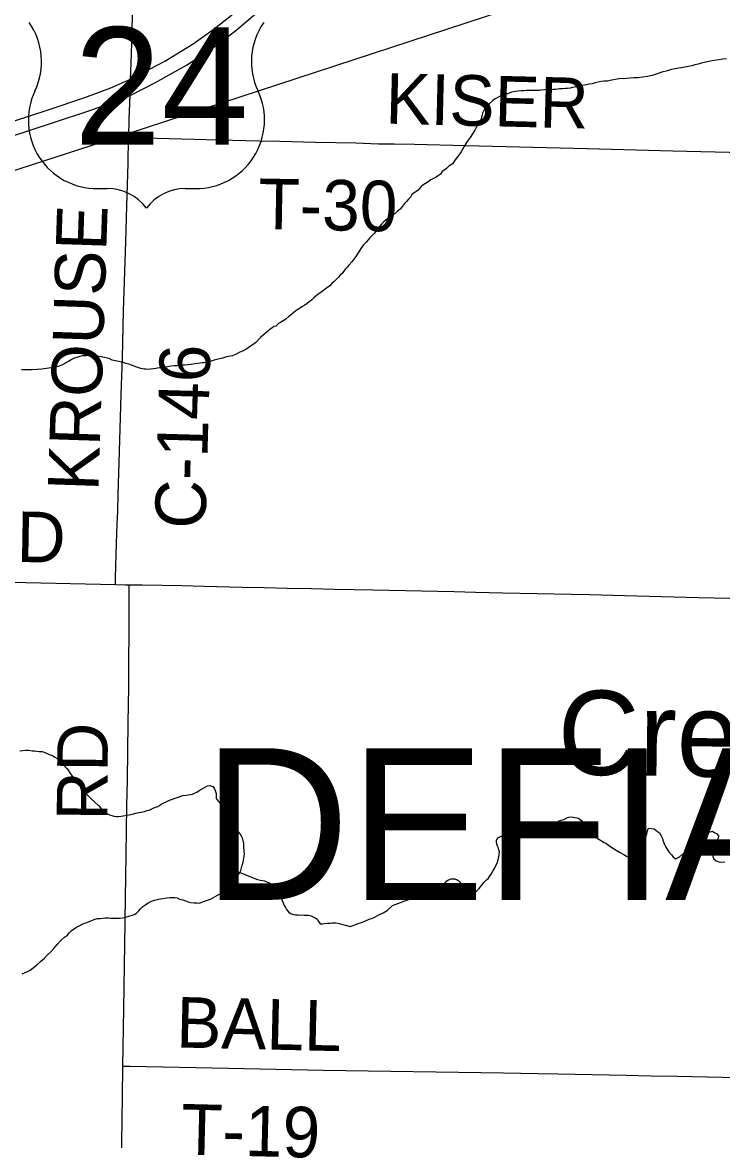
# Model space of a CAD drawing. Extents: x -483 to 680, y 0 to 440.
# Drawn here: x 121.3 to 160.7, y 248.8 to 311.6 of the extents above; entities that cross this region are included whole.
import ezdxf

# ---------------------------------------------------------------- set-up
doc = ezdxf.new("R2010")
doc.units = 0
for name, color, linetype in [('GM_X_County_Road', 7, 'Continuous'), ('GM_X_County_Road_Text', 7, 'Continuous'), ('GM_X_Minor_River', 7, 'Continuous'), ('GM_X_Minor_River_Text', 7, 'Continuous'), ('GM_X_Rail_Line', 7, 'Continuous'), ('GM_X_Township_Road', 7, 'Continuous'), ('GM_X_Township_Road_Text', 7, 'Continuous'), ('GM_X_Township_Text', 7, 'Continuous'), ('GM_X_US_Location', 7, 'Continuous'), ('GM_X_US_Route', 7, 'Continuous'), ('GM_X_US_Shield', 7, 'Continuous')]:
    doc.layers.add(name, color=color, linetype=linetype)

msp = doc.modelspace()

# ---------------------------------------------------------------- linework, layer by layer
at = {"layer": 'GM_X_County_Road'}
msp.add_line((127.32, 305.184), (127.345, 306.207), dxfattribs=at)
for points in [[(127.345, 306.207), (127.389, 307.543), (127.421, 308.449), (127.455, 309.354), (127.488, 310.473), (127.534, 312.026), (127.602, 314.637), (127.71, 318.272), (127.783, 320.572), (127.837, 322.374), (127.915, 324.829), (127.974, 326.631), (128.012, 327.812), (128.049, 329.241), (128.125, 331.945), (128.218, 335.032), (128.223, 336.234), (128.255, 337.539), (128.291, 339.124), (128.329, 340.865), (128.373, 342.512), (128.399, 343.693), (128.417, 344.657), (128.523, 349.753)], [(126.566, 280.056), (126.576, 280.424), (126.629, 282.382), (126.671, 283.468), (126.692, 284.183), (126.718, 285.115), (126.791, 287.537), (126.89, 290.737), (126.958, 292.787), (127.024, 295.427), (127.154, 299.309), (127.206, 301.329), (127.276, 303.72), (127.289, 304.124), (127.308, 304.745), (127.32, 305.184)], [(77.163, 281.006), (79.053, 280.972), (84.585, 280.875), (89.278, 280.783), (90.894, 280.761), (92.697, 280.726), (94.033, 280.704), (94.748, 280.692), (95.649, 280.674), (99.658, 280.588), (101.585, 280.553), (106.278, 280.468), (107.954, 280.425), (111.436, 280.37), (117.186, 280.256), (121.537, 280.166), (124.893, 280.092), (126.566, 280.056)], [(126.566, 280.056), (127.131, 280.044), (127.339, 280.04)], [(126.984, 252.996), (127.036, 256.212), (127.094, 259.847), (127.129, 262.427), (127.164, 264.85), (127.21, 267.615), (127.24, 269.076), (127.283, 272.276), (127.311, 274.295), (127.34, 278.798), (127.339, 280.04)], [(127.339, 280.04), (128.063, 280.038), (130.301, 279.993), (131.543, 279.96), (133.688, 279.907), (134.931, 279.884), (136.205, 279.855), (137.573, 279.829), (138.878, 279.8), (141.022, 279.752), (145.591, 279.656), (146.802, 279.622), (148.326, 279.586), (152.179, 279.515), (153.235, 279.487), (155.162, 279.431), (159.327, 279.332), (161.968, 279.265)], [(126.559, 227.882), (126.563, 228.311), (126.663, 233.22), (126.683, 234.619), (126.701, 235.985), (126.731, 237.85), (126.777, 240.833), (126.836, 243.317), (126.864, 244.529), (126.889, 246.518), (126.941, 249.874), (126.983, 252.888), (126.984, 252.996)]]:
    msp.add_lwpolyline(points, dxfattribs=at)
at = {"layer": 'GM_X_Minor_River'}
for points in [[(159.476, 309.352), (159.304, 309.3), (159.113, 309.248), (158.941, 309.195), (158.75, 309.162), (158.559, 309.129), (158.368, 309.096), (158.197, 309.062), (158.006, 309.029), (157.815, 308.996), (157.585, 308.926), (157.26, 308.839), (156.992, 308.751), (156.724, 308.663), (156.456, 308.594), (156.171, 308.563), (155.942, 308.531), (155.695, 308.518), (155.486, 308.505), (155.276, 308.491), (155.105, 308.476), (154.934, 308.481), (154.762, 308.447), (154.553, 308.414), (154.362, 308.381), (154.209, 308.347), (154.019, 308.333), (153.847, 308.319), (153.695, 308.285), (153.523, 308.251), (153.351, 308.198), (153.179, 308.165), (153.007, 308.131), (152.912, 308.115), (152.721, 308.081), (152.549, 308.048), (152.453, 308.012), (152.358, 307.996), (152.244, 307.98), (152.11, 307.945), (151.958, 307.93), (151.825, 307.933), (151.691, 307.918), (151.52, 307.903), (151.425, 307.887), (151.291, 307.871), (151.158, 307.875), (151.006, 307.859), (150.873, 307.863), (150.759, 307.866), (150.664, 307.849), (150.493, 307.835), (150.397, 307.818), (150.245, 307.822), (150.151, 307.824), (150.036, 307.808), (149.865, 307.813), (149.751, 307.815), (149.638, 307.819), (149.504, 307.803), (149.352, 307.788), (149.2, 307.773), (149.047, 307.758), (148.933, 307.742), (148.818, 307.725), (148.684, 307.672), (148.588, 307.636), (148.493, 307.62), (148.378, 307.585), (148.282, 307.53), (148.148, 307.477), (148.013, 307.404), (147.859, 307.332), (147.743, 307.24), (147.587, 307.092), (147.489, 306.981), (147.392, 306.888), (147.294, 306.758), (147.193, 306.533), (147.172, 306.438), (147.132, 306.344), (147.109, 306.212), (147.05, 306.119), (146.97, 305.969), (146.911, 305.875), (146.832, 305.744), (146.752, 305.594), (146.633, 305.388), (146.495, 305.183), (146.377, 305.015), (146.297, 304.884), (146.159, 304.66), (146.08, 304.529), (146, 304.398), (145.921, 304.248), (145.783, 304.081), (145.646, 303.913), (145.508, 303.689), (145.296, 303.562), (145.159, 303.432), (145.024, 303.322)], [(160.888, 309.601), (160.678, 309.569), (160.468, 309.536), (160.221, 309.504), (159.973, 309.454), (159.743, 309.403), (159.476, 309.352)], [(145.024, 303.322), (144.927, 303.267), (144.829, 303.118), (144.713, 303.045), (144.578, 302.953), (144.404, 302.844), (144.289, 302.79), (144.134, 302.68), (143.845, 302.497), (143.748, 302.424), (143.67, 302.331), (143.572, 302.219), (143.224, 301.962), (143.163, 301.831), (143.027, 301.702), (142.91, 301.572), (142.812, 301.46), (142.694, 301.311), (142.557, 301.144), (142.402, 301.015), (142.266, 300.886), (142.131, 300.813), (141.938, 300.685), (141.783, 300.556), (141.627, 300.408), (141.53, 300.316), (141.413, 300.186), (141.295, 300.037), (141.216, 299.925), (141.118, 299.794), (140.982, 299.665), (140.865, 299.535), (140.767, 299.424), (140.65, 299.294), (140.513, 299.164), (140.395, 298.996), (140.079, 298.492), (139.961, 298.343), (139.843, 298.194), (139.687, 298.008), (139.589, 297.897), (139.511, 297.804), (139.374, 297.636), (139.295, 297.524), (139.198, 297.432), (139.1, 297.32), (138.964, 297.191), (138.847, 297.08), (138.73, 296.969), (138.613, 296.839), (138.42, 296.711), (138.265, 296.601), (138.11, 296.472), (137.955, 296.362), (137.82, 296.252), (137.703, 296.16), (137.586, 296.03), (137.451, 295.938), (137.335, 295.846), (137.199, 295.755), (137.084, 295.682), (136.929, 295.591), (136.814, 295.518), (136.697, 295.426), (136.601, 295.353), (136.484, 295.242), (136.31, 295.113), (136.135, 294.966), (135.981, 294.875), (135.846, 294.783), (135.73, 294.729), (135.575, 294.581), (135.479, 294.546), (135.363, 294.473), (135.247, 294.381), (135.111, 294.27), (134.956, 294.141), (134.859, 294.068), (134.723, 293.938), (134.45, 293.661), (134.295, 293.551), (134.16, 293.44), (134.005, 293.33), (133.851, 293.239), (133.697, 293.167), (133.563, 293.114), (133.39, 293.023), (133.139, 292.897), (132.815, 292.848), (132.586, 292.778), (132.338, 292.727), (132.108, 292.657), (131.897, 292.587), (131.706, 292.554), (131.554, 292.52), (131.439, 292.504), (131.325, 292.488), (131.192, 292.472), (131.02, 292.457), (130.829, 292.424), (130.639, 292.391)], [(130.639, 292.391), (130.449, 292.377), (130.278, 292.381), (130.144, 292.366), (130.011, 292.35), (129.859, 292.335), (129.687, 292.321), (129.516, 292.287), (129.344, 292.273), (129.21, 292.238), (129.115, 292.221), (129.02, 292.224), (128.925, 292.207), (128.829, 292.191), (128.696, 292.175), (128.544, 292.16), (128.429, 292.144), (128.277, 292.148), (128.183, 292.151), (128.088, 292.172), (127.994, 292.193), (127.881, 292.234), (127.768, 292.275), (127.617, 292.317), (127.467, 292.378), (127.316, 292.439), (127.146, 292.481), (126.995, 292.523), (126.561, 292.629), (126.391, 292.671), (126.222, 292.752), (125.958, 292.815), (125.769, 292.858), (125.561, 292.883), (125.409, 292.906), (125.277, 292.909), (125.182, 292.911), (125.087, 292.914), (124.992, 292.916), (124.897, 292.9), (124.802, 292.902), (124.707, 292.905), (124.573, 292.87), (124.458, 292.835), (124.324, 292.8), (124.209, 292.747), (124.074, 292.674), (123.92, 292.583), (123.785, 292.511), (123.67, 292.438), (123.554, 292.383), (123.343, 292.313), (123.171, 292.26), (122.943, 292.228), (122.695, 292.197), (122.428, 292.166), (122.161, 292.135), (121.895, 292.122), (121.61, 292.111), (121.439, 292.115), (121.287, 292.119)], [(121.189, 270.719), (121.361, 270.733), (121.532, 270.748), (121.703, 270.743), (121.892, 270.719), (122.025, 270.716), (122.138, 270.694), (122.29, 270.671), (122.442, 270.667), (122.649, 270.605), (122.836, 270.505), (123.025, 270.444), (123.156, 270.364), (123.287, 270.285), (123.399, 270.206), (123.547, 270.05), (123.658, 269.933), (123.75, 269.817), (123.842, 269.72), (123.916, 269.623), (124.007, 269.469), (124.136, 269.294), (124.246, 269.159), (124.338, 269.042), (124.43, 268.926), (124.504, 268.829), (124.577, 268.713), (124.725, 268.558), (124.78, 268.461), (124.909, 268.306), (125.184, 268.04)], [(129.609, 267.943), (130.357, 268.204), (130.547, 268.218), (130.643, 268.234), (130.757, 268.251), (130.891, 268.285), (131.006, 268.339), (131.14, 268.393), (131.276, 268.484), (131.43, 268.575), (131.603, 268.665), (131.738, 268.738), (131.871, 268.754), (132.041, 268.711), (132.115, 268.614), (132.168, 268.48), (132.221, 268.308), (132.233, 268.023), (132.341, 267.884)], [(125.184, 268.04), (125.632, 267.614), (125.724, 267.516), (125.872, 267.359), (126.02, 267.24), (126.113, 267.179), (126.226, 267.119), (126.358, 267.076), (126.47, 267.034), (126.604, 267.03), (126.718, 267.026), (126.89, 267.039), (127.119, 267.07), (127.33, 267.12), (127.579, 267.168), (127.79, 267.218), (128.02, 267.268), (128.193, 267.3), (128.328, 267.353), (128.462, 267.386), (128.578, 267.439), (128.694, 267.493), (128.81, 267.546), (128.906, 267.561), (129.041, 267.633), (129.139, 267.706), (129.607, 267.943)], [(132.347, 262.615), (132.482, 262.686), (132.579, 262.74), (132.659, 262.832), (132.758, 262.962), (132.897, 263.129), (133.054, 263.295), (133.212, 263.461), (133.369, 263.627), (133.488, 263.756), (133.549, 263.868), (133.609, 263.98), (133.652, 264.131), (133.695, 264.282), (133.738, 264.451), (133.81, 264.906), (133.797, 265.096), (133.786, 265.344), (133.772, 265.515), (133.739, 265.65), (133.706, 265.803), (133.652, 265.919), (133.58, 266.055), (133.47, 266.172), (133.379, 266.309), (133.232, 266.485), (133.104, 266.641), (132.994, 266.778), (132.921, 266.876), (132.867, 266.973), (132.813, 267.069), (132.778, 267.166), (132.724, 267.282), (132.671, 267.398), (132.618, 267.533), (132.564, 267.629), (132.454, 267.766), (132.341, 267.884)], [(147.675, 263.777), (147.776, 263.945), (147.857, 264.094), (147.918, 264.226), (147.998, 264.356), (148.039, 264.45), (148.063, 264.582), (148.106, 264.752), (148.134, 265.036), (148.1, 265.152), (148.084, 265.247), (148.031, 265.363), (147.995, 265.46), (147.981, 265.593), (147.984, 265.688), (148.045, 265.819), (148.238, 265.908), (148.352, 265.904), (148.561, 265.878), (148.656, 265.875), (148.751, 265.872), (148.904, 265.886), (149.018, 265.882), (149.171, 265.896), (149.323, 265.891), (149.514, 265.904), (149.744, 265.953), (149.897, 265.986), (150.032, 266.038), (150.226, 266.127), (150.457, 266.215), (150.689, 266.321), (150.882, 266.391), (151.017, 266.462), (151.115, 266.535), (151.288, 266.605), (151.484, 266.77), (151.753, 266.856), (151.928, 266.946), (152.043, 266.98), (152.196, 266.994), (152.291, 266.991), (152.574, 266.924), (152.779, 266.765), (152.872, 266.686), (152.964, 266.607), (153.056, 266.509), (153.202, 266.294), (153.311, 266.139), (153.421, 266.002), (153.513, 265.904), (153.624, 265.805), (153.811, 265.685), (153.923, 265.624), (154.016, 265.563), (154.11, 265.522), (154.259, 265.403), (154.389, 265.323), (154.539, 265.223), (154.707, 265.122), (154.894, 265.021), (155.137, 264.879), (155.287, 264.798), (155.4, 264.757), (155.513, 264.734), (155.609, 264.75), (155.802, 264.819), (155.978, 264.966), (156.076, 265.076), (156.136, 265.17), (156.179, 265.32), (156.222, 265.452), (156.263, 265.565), (156.306, 265.716), (156.348, 265.828), (156.39, 265.941), (156.412, 266.055), (156.435, 266.168), (156.477, 266.281), (156.518, 266.374), (156.84, 266.326), (157.026, 266.186), (157.138, 266.107), (157.227, 265.932), (157.298, 265.778), (157.314, 265.682), (157.367, 265.547), (157.421, 265.45), (157.475, 265.335), (157.529, 265.238), (157.583, 265.141), (157.656, 265.043), (157.803, 264.867), (157.894, 264.75), (158.024, 264.65), (158.14, 264.704), (158.256, 264.757), (158.432, 264.903), (158.567, 264.956), (158.724, 265.103), (158.804, 265.214)], [(158.804, 265.214), (158.884, 265.326), (158.964, 265.475), (159.044, 265.587), (159.182, 265.734), (159.281, 265.845), (159.418, 265.955), (159.534, 266.008), (159.726, 266.078), (159.919, 266.147), (160.111, 266.198), (160.241, 266.099), (160.335, 266.058), (160.446, 265.94), (160.422, 265.807), (160.381, 265.695), (160.339, 265.582), (160.298, 265.488), (160.256, 265.356), (160.232, 265.224), (160.191, 265.111), (160.148, 264.96), (160.123, 264.771), (160.194, 264.635), (160.325, 264.536), (160.475, 264.474), (160.627, 264.45), (160.799, 264.482)], [(133.549, 263.868), (134.545, 263.473), (134.716, 263.449), (134.848, 263.425), (134.943, 263.403), (135.055, 263.342), (135.225, 263.298), (135.393, 263.179), (135.504, 263.08), (135.558, 262.983), (135.631, 262.885), (135.741, 262.748), (135.832, 262.612), (135.885, 262.496), (135.936, 262.304), (135.989, 262.169), (136.041, 262.016), (136.113, 261.899), (136.168, 261.802), (136.296, 261.665), (136.408, 261.566), (136.577, 261.522), (136.691, 261.499), (136.824, 261.495), (136.957, 261.471), (137.052, 261.487), (137.167, 261.483), (137.281, 261.479), (137.414, 261.475), (137.565, 261.432), (137.678, 261.39), (137.79, 261.329), (137.902, 261.249), (137.974, 261.114), (138.065, 260.997), (138.198, 260.992), (138.313, 261.007), (138.466, 261.021), (138.638, 261.035), (138.733, 261.051), (138.828, 261.047), (138.943, 261.044), (139.056, 261.021), (139.208, 260.997), (139.34, 260.954), (139.472, 260.912), (139.566, 260.89), (139.755, 260.845), (139.928, 260.897), (140.14, 260.984), (140.391, 261.071), (140.622, 261.159), (140.815, 261.247), (141.008, 261.317), (141.201, 261.406), (141.395, 261.513), (141.607, 261.601), (141.84, 261.746), (142.135, 262.021), (142.579, 262.197), (142.829, 262.284), (143.002, 262.335), (143.137, 262.387), (143.291, 262.458), (143.447, 262.567), (143.661, 262.693), (143.835, 262.783), (143.99, 262.873), (144.106, 262.926), (144.279, 262.977), (144.393, 262.973), (144.546, 262.987), (144.68, 263.002), (144.776, 263.037), (144.893, 263.109), (145.089, 263.292), (145.188, 263.403), (145.285, 263.457), (145.42, 263.51), (145.534, 263.525), (145.629, 263.522), (145.761, 263.46), (145.91, 263.36), (145.999, 263.167), (145.993, 262.977), (145.95, 262.826), (145.965, 262.693), (146.058, 262.632), (146.153, 262.61), (146.266, 262.587), (146.381, 262.622), (146.535, 262.674), (146.67, 262.707), (146.826, 262.816), (147.002, 262.981), (147.141, 263.148), (147.261, 263.315), (147.418, 263.462), (147.516, 263.554), (147.576, 263.647), (147.675, 263.777)], [(121.332, 258.189), (121.583, 258.295), (121.776, 258.383), (121.952, 258.51), (122.148, 258.694), (122.364, 258.877), (122.579, 259.06), (122.756, 259.245), (122.933, 259.41), (123.111, 259.613), (123.289, 259.835), (123.506, 260.057), (123.702, 260.24), (123.877, 260.349), (123.976, 260.478), (124.055, 260.571), (124.153, 260.644), (124.309, 260.753), (124.406, 260.825), (124.522, 260.879), (124.677, 260.949), (124.831, 261.02), (124.966, 261.073), (125.179, 261.161), (125.371, 261.231), (125.544, 261.282), (125.716, 261.295), (125.85, 261.31), (125.984, 261.324), (126.079, 261.321), (126.174, 261.318), (126.269, 261.315), (126.402, 261.31), (126.802, 261.316), (126.955, 261.33), (127.127, 261.362), (127.262, 261.396), (127.377, 261.43), (127.531, 261.482), (127.647, 261.535), (127.744, 261.589), (127.862, 261.699), (127.98, 261.828), (128.099, 261.958), (128.274, 262.085), (128.41, 262.175), (128.584, 262.265), (128.757, 262.316), (128.988, 262.384), (129.218, 262.415), (129.447, 262.445), (129.638, 262.477), (129.772, 262.472), (129.905, 262.468), (130.037, 262.444), (130.169, 262.383), (130.358, 262.339), (130.508, 262.277), (130.659, 262.233), (130.81, 262.19), (130.981, 262.166), (131.133, 262.161), (131.266, 262.156), (131.381, 262.19), (131.516, 262.243), (131.689, 262.294), (131.901, 262.382), (132.173, 262.525), (132.347, 262.615)]]:
    msp.add_lwpolyline(points, dxfattribs=at)
at = {"layer": 'GM_X_Rail_Line'}
msp.add_lwpolyline([(52.231, 281.076), (127.278, 305.392), (222.338, 336.549), (257.887, 348.093), (262.457, 349.692), (266.922, 351.391), (271.85, 353.786), (276.063, 355.851), (279.587, 357.722), (282.074, 359.273), (284.73, 360.909), (286.844, 362.348), (291.566, 365.767), (297.907, 370.986), (306.481, 378.212), (309.709, 381.296), (311.628, 383.535), (313.46, 385.542), (315.408, 389.44), (316.608, 391.805), (318.711, 395.95)], dxfattribs=at)
at = {"layer": 'GM_X_Township_Road'}
for points in [[(127.32, 305.184), (127.777, 305.171), (128.895, 305.14), (131.66, 305.068), (134.643, 304.982), (135.793, 304.966), (137.812, 304.921), (140.08, 304.871), (141.354, 304.826), (142.224, 304.815), (143.374, 304.791), (146.233, 304.728), (153.068, 304.547), (157.884, 304.428), (161.83, 304.33), (162.949, 304.309), (164.129, 304.277), (168.914, 304.153), (174.01, 304.032), (176.216, 303.98), (177.302, 303.96), (177.765, 303.951)], [(126.984, 252.996), (127.39, 252.988), (132.921, 252.889), (138.233, 252.761), (148.362, 252.616), (150.32, 252.58), (151.438, 252.56), (155.26, 252.481), (156.658, 252.457), (158.118, 252.431), (160.665, 252.367), (163.834, 252.289)]]:
    msp.add_lwpolyline(points, dxfattribs=at)
at = {"layer": 'GM_X_US_Route'}
for points in [[(127.389, 307.543), (128.784, 308.252), (130.551, 309.246), (132.146, 310.29), (133.329, 311.195), (134.562, 312.238)], [(127.421, 308.449), (129.343, 309.46), (130.937, 310.446), (132.113, 311.277), (133.189, 312.115)], [(77.288, 291.856), (122.784, 306.734), (124.838, 307.43), (126.301, 307.972), (127.421, 308.449)], [(77.267, 290.998), (123.029, 305.999), (125.191, 306.715), (126.663, 307.257), (127.389, 307.543)]]:
    msp.add_lwpolyline(points, dxfattribs=at)
at = {"layer": 'GM_X_US_Shield'}
for p, q in [((125.561, 302.305), (126.11, 302.305)), ((130.504, 302.305), (131.054, 302.305))]:
    msp.add_line(p, q, dxfattribs=at)
for centre, radius, start, end in [((118.566, 309.438), 3.845, 334.54712, 35.00093), ((138.049, 309.438), 3.845, 144.99907, 205.45288), ((125.518, 306.15), 3.845, 154.83192, 270.63826), ((131.097, 306.15), 3.845, 269.36174, 25.16808), ((126.11, 299.559), 2.747, 36.8699, 90), ((130.504, 299.559), 2.747, 90, 143.1301)]:
    msp.add_arc(centre, radius, start, end, dxfattribs=at)

# ---------------------------------------------------------------- texts
at = {"layer": 'GM_X_County_Road_Text'}
for s, rotation, p in [('KROUSE', 88.11347, (125.605, 285.284)), ('C-146', 88.36352, (131.616, 283.158)), ('RD', 359.01741, (118.258, 281.372)), ('RD', 89.50665, (126.106, 266.79))]:
    msp.add_text(s, height=2.8409, rotation=rotation, dxfattribs=at).set_placement(p)
at = {"layer": 'GM_X_Minor_River_Text'}
msp.add_text('Creek', height=4.7372, rotation=359.17665, dxfattribs=at).set_placement((151.386, 269.388))
at = {"layer": 'GM_X_Township_Road_Text'}
for s, rotation, p in [('KISER', 358.5792, (141.715, 305.956)), ('T-30', 358.95969, (134.572, 300.033)), ('BALL', 358.6882, (129.961, 254.045)), ('T-19', 358.58501, (130.227, 248.034))]:
    msp.add_text(s, height=2.8409, rotation=rotation, dxfattribs=at).set_placement(p)
at = {"layer": 'GM_X_Township_Text'}
msp.add_text('DEFIANCE', height=8.5227, rotation=0.00001, dxfattribs=at).set_placement((131.49, 262.337))
at = {"layer": 'GM_X_US_Location'}
for s in ['0', '/']:
    msp.add_text(s, height=0.00947, dxfattribs=at).set_placement((128.304, 308.021))
msp.add_text('24', height=0.00947, rotation=0.00001, dxfattribs=at).set_placement((126.349, 306.061))
at = {"layer": 'GM_X_US_Shield'}
msp.add_text('24', height=6.5918, dxfattribs=at).set_placement((124.24, 304.777))

doc.saveas('drawing.dxf')
